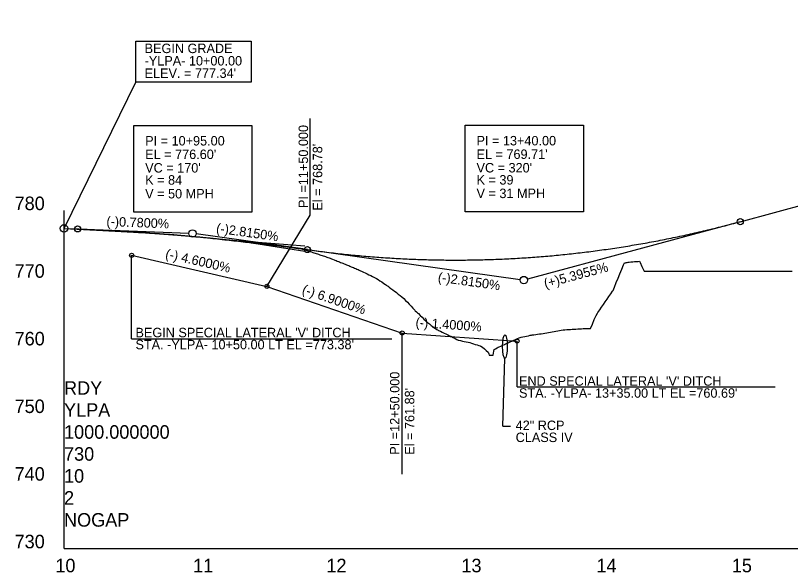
# Model space of a CAD drawing. Extents: x 579185 to 595036, y -53221 to -44640.
# Drawn here: x 579255 to 579828, y -51053 to -50642 of the extents above; entities that cross this region are included whole.
import ezdxf

# ---------------------------------------------------------------- set-up
doc = ezdxf.new("R2010")
doc.units = 0
for name, color, linetype in [('Default', 7, 'Continuous'), ('Exist Profile Cell', 7, 'Continuous'), ('Exist Vertical Profile Ground Line', 7, 'Continuous'), ('Exist Vertical Profile Horizontal Axis Label Major', 7, 'Continuous'), ('Exist Vertical Profile Vertical Axis Label', 7, 'Continuous'), ('Prop Grid Mask', 7, 'Continuous'), ('Prop PFL Cross Pipe CELL', 7, 'Continuous'), ('Prop Vertical Profile Curve Label', 7, 'Continuous'), ('Prop Vertical Profile Ditch Grade Left', 7, 'Continuous'), ('Prop Vertical Profile Ditch Grade Left Label', 7, 'Continuous'), ('Prop Vertical Profile Ditch Grade Right Label', 7, 'Continuous'), ('Prop Vertical Profile Grade', 7, 'Continuous'), ('Prop Vertical Profile Grade Label', 7, 'Continuous'), ('Prop VPI Ditch Grade Left Label', 7, 'Continuous'), ('Prop VPI Label', 7, 'Continuous')]:
    doc.layers.add(name, color=color, linetype=linetype)

msp = doc.modelspace()

# ---------------------------------------------------------------- linework, layer by layer
at = {"layer": 'Default'}
for points in [[(579290.38, -50799.07), (579318.98, -50800.49), (579368.86, -50803.42), (579418.21, -50807.98), (579468.45, -50812.02)], [(579290.38, -50799.07), (579318.98, -50800.49), (579368.86, -50803.42), (579418.21, -50808.04), (579468.45, -50815.9)]]:
    msp.add_lwpolyline(points, dxfattribs=at)
at = {"layer": 'Exist Profile Cell'}
for q in [(579290.38, -50785.8), (580388.15, -51035.8), (579290.38, -51035.8)]:
    msp.add_line((579290.38, -51035.8), q, dxfattribs=at)
at = {"layer": 'Exist Vertical Profile Ground Line'}
for points in [[(579290.38, -50799.07), (579297.26, -50799.41), (579300.7, -50799.58), (579304.13, -50799.75), (579305.9, -50799.84), (579307.57, -50799.92), (579308.34, -50799.96), (579311.01, -50800.09), (579314.45, -50800.26), (579317.88, -50800.44), (579321.32, -50800.61), (579324.76, -50800.79), (579326.48, -50800.88), (579328.2, -50800.97), (579329.92, -50801.06), (579331.27, -50801.13), (579331.63, -50801.15), (579332.4, -50801.19), (579333.35, -50801.25), (579335.07, -50801.35), (579336.79, -50801.45), (579338.51, -50801.55), (579340.23, -50801.66), (579341.95, -50801.76), (579343.67, -50801.87), (579345.38, -50801.98), (579347.1, -50802.08), (579348.82, -50802.19), (579350.54, -50802.3), (579352.26, -50802.41), (579353.52, -50802.49), (579353.98, -50802.52), (579355.7, -50802.63), (579357.42, -50802.74), (579358.51, -50802.82), (579359.13, -50802.86), (579360.85, -50802.99), (579362.57, -50803.11), (579364.29, -50803.24), (579366.08, -50803.38), (579367.73, -50803.5), (579369.45, -50803.63), (579371.17, -50803.76), (579372.88, -50803.89), (579374.6, -50804.02), (579376.32, -50804.15), (579378.04, -50804.29), (579379.76, -50804.42), (579381.48, -50804.56), (579383.2, -50804.7), (579384.92, -50804.87), (579386.63, -50805.03), (579388.35, -50805.2), (579390.07, -50805.37), (579391.79, -50805.54), (579393.51, -50805.71), (579395.23, -50805.89), (579396.95, -50806.06), (579398.67, -50806.24), (579400.38, -50806.42), (579402.1, -50806.6), (579403.82, -50806.83), (579405.54, -50807.06), (579406.15, -50807.14), (579407.26, -50807.21), (579408.98, -50807.37), (579409.29, -50807.4), (579410.7, -50807.55), (579412.42, -50807.74), (579414.13, -50807.94), (579415.85, -50808.13), (579417.57, -50808.33), (579419.29, -50808.53), (579421.01, -50808.73), (579422.73, -50808.94), (579424.45, -50809.15), (579426.17, -50809.36), (579427.88, -50809.57), (579428.74, -50809.68), (579429.06, -50809.72), (579429.6, -50809.78), (579430.46, -50809.89), (579431.32, -50810), (579432.18, -50810.11), (579433.04, -50810.22), (579433.9, -50810.32), (579434.76, -50810.43), (579435.71, -50810.56), (579436.48, -50810.65), (579437.34, -50810.75), (579438.2, -50810.85), (579439.06, -50810.95), (579439.92, -50811.05), (579440.77, -50811.15), (579441.66, -50811.26), (579442.49, -50811.31), (579443.35, -50811.37), (579444.21, -50811.43), (579445.07, -50811.49), (579445.93, -50811.55), (579446.79, -50811.61)], [(579446.79, -50811.61), (579447.65, -50811.67), (579448.58, -50811.73), (579449.37, -50811.83), (579450.23, -50811.94), (579451.09, -50812.06), (579451.95, -50812.17), (579452.81, -50812.28), (579453.67, -50812.4), (579454.52, -50812.51), (579455.38, -50812.63), (579456.24, -50812.75), (579457.1, -50812.86), (579457.96, -50812.98), (579458.82, -50813.1), (579459.68, -50813.22), (579460.54, -50813.34), (579461.4, -50813.46), (579462.26, -50813.58), (579463.12, -50813.7), (579463.98, -50813.82), (579464.84, -50813.95), (579465.94, -50814.15), (579466.65, -50814.36), (579467.42, -50814.6), (579468.27, -50814.86), (579469.13, -50815.13), (579469.99, -50815.4), (579470.85, -50815.67), (579471.71, -50815.95), (579472.57, -50816.22), (579473.43, -50816.5), (579474.29, -50816.78), (579475.15, -50817.06), (579476.01, -50817.35), (579476.87, -50817.63), (579477.73, -50817.92), (579478.59, -50818.21), (579479.45, -50818.5), (579480.31, -50818.79), (579481.17, -50819.09), (579482.02, -50819.37), (579482.88, -50819.66), (579483.74, -50819.94), (579484.6, -50820.23), (579485.46, -50820.53), (579486.32, -50820.83), (579487.18, -50821.18), (579488.04, -50821.53), (579488.9, -50821.88), (579490.02, -50822.35), (579490.62, -50822.57), (579491.48, -50822.89), (579492.34, -50823.22), (579493.2, -50823.54), (579494.06, -50823.87), (579494.92, -50824.2), (579495.77, -50824.53), (579496.63, -50824.87), (579497.49, -50825.2), (579498.35, -50825.54), (579499.21, -50825.89), (579500.07, -50826.23), (579500.93, -50826.58), (579501.79, -50826.93), (579502.81, -50827.35), (579503.51, -50827.65), (579504.37, -50828.02), (579505.23, -50828.4), (579506.09, -50828.78), (579506.95, -50829.16), (579507.81, -50829.55), (579508.67, -50829.94), (579509.52, -50830.33), (579510.38, -50830.72), (579511.74, -50831.35), (579513.09, -50831.98), (579514.45, -50832.62), (579515.8, -50833.27), (579517.16, -50833.93), (579518.51, -50834.59), (579519.87, -50835.33), (579521.33, -50836.14), (579522.58, -50836.94), (579523.93, -50837.81), (579525.29, -50838.68), (579526.82, -50839.68), (579528, -50840.46), (579528.88, -50841.05), (579529.35, -50841.4), (579529.94, -50841.84), (579530.71, -50842.42), (579532.06, -50843.44), (579533.42, -50844.47), (579534.78, -50845.51), (579535.1, -50845.77), (579536.13, -50846.54), (579537.49, -50847.57), (579538.84, -50848.62), (579540.2, -50849.69), (579541.55, -50850.82)], [(579652.66, -50875.38), (579654.02, -50875.14), (579655.37, -50874.89), (579656.73, -50874.65), (579658.08, -50874.4), (579659.44, -50874.16), (579660.79, -50873.95), (579662.15, -50873.88), (579663.5, -50873.81), (579664.86, -50873.74), (579666.21, -50873.66), (579667.57, -50873.59), (579668.92, -50873.51), (579670.28, -50873.43), (579671.63, -50873.35), (579672.99, -50873.26), (579674.34, -50873.18), (579675.17, -50873.13), (579675.7, -50873.13), (579677.05, -50873.14), (579678.41, -50873.14), (579679.76, -50873.11), (579681.12, -50869.8), (579682.47, -50866.49), (579683.08, -50865.02), (579683.92, -50863.37), (579684.77, -50861.75), (579685.18, -50861.15), (579686.54, -50859.2), (579687.9, -50857.26), (579689.25, -50855.27), (579690.61, -50853.28), (579691.96, -50851.3), (579693.32, -50849.32), (579694.67, -50847.35), (579696.03, -50845.39), (579696.35, -50844.92), (579697.38, -50842.41), (579698.74, -50839.11), (579700.09, -50835.83), (579701.45, -50832.56), (579702.8, -50829.3), (579704.16, -50826.05), (579704.76, -50824.62), (579705.51, -50824.43), (579706.04, -50824.31), (579706.87, -50824.15), (579707.54, -50824.02), (579708.22, -50823.96), (579709.58, -50823.84), (579710.93, -50823.73), (579712.29, -50823.61), (579713.64, -50823.49), (579714, -50823.46), (579715, -50823.41), (579715.88, -50823.37), (579716.35, -50824.36), (579717.71, -50827.18), (579719.26, -50830.66), (579719.87, -50830.66), (579720.42, -50830.66), (579721.77, -50830.66), (579723.13, -50830.66), (579724.48, -50830.66), (579725.84, -50830.66), (579727.19, -50830.66), (579728.55, -50830.66), (579729.9, -50830.66), (579730.94, -50830.66), (579731.26, -50830.66), (579732.61, -50830.66), (579733.97, -50830.66), (579735.32, -50830.66), (579736.68, -50830.66), (579738.03, -50830.66), (579739.39, -50830.66), (579740.74, -50830.66), (579742.1, -50830.66), (579743.45, -50830.66), (579744.81, -50830.66), (579746.16, -50830.66), (579747.52, -50830.66), (579748.87, -50830.66), (579750.23, -50830.66), (579751.58, -50830.66), (579752.94, -50830.66), (579754.29, -50830.66), (579755.65, -50830.66), (579757, -50830.66), (579758.36, -50830.66), (579759.71, -50830.66), (579761.07, -50830.66), (579761.58, -50830.66), (579762.42, -50830.66), (579763.78, -50830.66), (579765.13, -50830.66), (579766.49, -50830.66), (579766.95, -50830.66), (579767.84, -50830.66), (579769.2, -50830.66), (579770.55, -50830.66)], [(579770.55, -50830.66), (579771.22, -50830.66), (579771.91, -50830.66), (579773.37, -50830.66), (579774.62, -50830.66), (579775.97, -50830.66), (579777.33, -50830.66), (579777.94, -50830.66), (579778.68, -50830.66), (579780.04, -50830.66), (579781.39, -50830.66), (579782.75, -50830.66), (579784.1, -50830.66), (579785.46, -50830.66), (579786.81, -50830.66), (579788.17, -50830.66), (579789.52, -50830.66), (579790.88, -50830.66), (579792.23, -50830.66), (579793.59, -50830.66), (579794.94, -50830.66), (579796.3, -50830.66), (579797.65, -50830.66), (579799.01, -50830.66), (579800.36, -50830.66), (579801.72, -50830.66), (579803.07, -50830.66), (579804.43, -50830.66), (579805.78, -50830.66), (579807.14, -50830.66), (579808.49, -50830.66), (579809.85, -50830.66), (579811.2, -50830.66), (579812.56, -50830.66), (579813.18, -50830.66), (579813.91, -50830.66), (579815.27, -50830.66), (579816.66, -50830.66), (579817.98, -50830.66), (579819.33, -50830.66), (579820.69, -50830.66), (579822.04, -50830.66), (579823.4, -50830.66), (579824.79, -50830.66), (579826.11, -50830.66), (579827.46, -50830.66), (579828.82, -50830.66)], [(579541.55, -50850.82), (579542.91, -50852.25), (579544.26, -50853.69), (579545.62, -50855.13), (579546.97, -50856.58), (579548.33, -50858.05), (579549.68, -50859.52), (579550.06, -50859.93), (579551.04, -50860.82), (579551.81, -50861.54), (579552.39, -50862.09), (579553.75, -50863.41), (579555.1, -50864.73), (579556.46, -50866.06), (579557.81, -50867.4), (579558.51, -50868.1), (579559.17, -50868.61), (579560.52, -50869.67), (579561.88, -50870.74), (579563.23, -50871.81), (579564.07, -50872.47), (579564.59, -50872.81), (579565.94, -50873.7), (579566.97, -50874.38), (579567.3, -50874.52), (579568.65, -50875.14), (579570.01, -50875.76), (579570.58, -50876.02), (579571.36, -50876.4), (579572.72, -50877.07), (579574.07, -50877.73), (579575.43, -50878.4), (579576.31, -50878.83), (579576.78, -50879.07), (579578.14, -50879.77), (579578.72, -50880.07), (579579.49, -50880.48), (579580.85, -50881.19), (579581.76, -50881.67), (579582.2, -50881.78), (579583.56, -50882.05), (579584.91, -50882.31), (579586.27, -50882.58), (579587.62, -50882.84), (579589.15, -50883.13), (579590.33, -50883.51), (579591.69, -50883.94), (579593.04, -50884.37), (579594.4, -50884.8), (579595.75, -50885.22), (579597.11, -50885.64), (579597.97, -50885.91), (579598.46, -50886.09), (579599.82, -50886.83), (579601.17, -50888.04), (579602.53, -50889.24), (579603.91, -50890.46), (579604.46, -50891.9), (579604.81, -50892.8), (579605.31, -50892.73), (579606.59, -50892.79), (579607.6, -50892.84), (579608.05, -50889.89), (579608.49, -50888.7), (579609.3, -50888.21), (579610.66, -50887.39), (579611.4, -50886.93), (579612.01, -50886.67), (579613.37, -50886.09), (579614.35, -50885.67), (579614.72, -50885.49), (579616.08, -50884.81), (579616.73, -50884.48), (579617.43, -50884.16), (579618.79, -50883.54), (579620.14, -50882.92), (579621.5, -50882.31), (579622.85, -50881.69), (579624.21, -50881.08), (579625.56, -50880.44), (579626.92, -50879.84), (579628.27, -50879.55), (579629.63, -50879.26), (579630.98, -50878.97), (579632.34, -50878.68), (579633.69, -50878.39), (579635.05, -50878.1), (579636, -50877.9), (579636.4, -50877.85), (579637.76, -50877.67), (579639.25, -50877.48), (579640.47, -50877.3), (579641.82, -50877.11), (579643.18, -50876.92), (579644.53, -50876.73), (579645.89, -50876.53), (579647.24, -50876.33), (579648.65, -50876.11), (579649.95, -50875.87), (579651.31, -50875.63), (579652.66, -50875.38)]]:
    msp.add_lwpolyline(points, dxfattribs=at)
at = {"layer": 'Prop Grid Mask'}
for points in [[(579343.41, -50660.71), (579428.8, -50660.71), (579428.8, -50690.9), (579343.41, -50690.9)], [(579342, -50722.89), (579429.36, -50722.89), (579429.36, -50787.07), (579342, -50787.07)], [(579587, -50722.66), (579674.36, -50722.66), (579674.36, -50786.83), (579587, -50786.83)]]:
    msp.add_lwpolyline(points, close=True, dxfattribs=at)
at = {"layer": 'Prop PFL Cross Pipe CELL'}
msp.add_ellipse((579616.38, -50886.4), major_axis=(0, 8.75), ratio=0.2, dxfattribs=at)
at = {"layer": 'Prop Vertical Profile Curve Label'}
msp.add_line((579290.38, -50799.07), (579343.41, -50690.9), dxfattribs=at)
for centre in [(579790.38, -50794.1), (579300.38, -50799.46), (579470.38, -50814.74), (579470.38, -50814.74)]:
    msp.add_circle(centre, 2.25, dxfattribs=at)
at = {"layer": 'Prop Vertical Profile Ditch Grade Left'}
msp.add_lwpolyline([(579340.38, -50818.9), (579440.38, -50841.9), (579540.38, -50876.4), (579625.38, -50882.35)], dxfattribs=at)
at = {"layer": 'Prop Vertical Profile Ditch Grade Left Label'}
for p, q in [((579472.35, -50789.18), (579472.35, -50717.76)), ((579440.38, -50841.9), (579472.35, -50789.18)), ((579340.38, -50880.65), (579340.38, -50818.9)), ((579540.38, -50980.69), (579540.38, -50876.4)), ((579340.38, -50880.65), (579532.84, -50880.65)), ((579625.38, -50916.13), (579625.38, -50882.35)), ((579625.38, -50916.13), (579816.19, -50916.13))]:
    msp.add_line(p, q, dxfattribs=at)
for centre in [(579340.38, -50818.9), (579440.38, -50841.9), (579540.38, -50876.4), (579625.38, -50882.35)]:
    msp.add_circle(centre, 1.5, dxfattribs=at)
at = {"layer": 'Prop Vertical Profile Ditch Grade Right Label'}
for q in [(579616.38, -50895.15), (579620.42, -50945.27)]:
    msp.add_line((579614.8, -50945.27), q, dxfattribs=at)
at = {"layer": 'Prop Vertical Profile Grade'}
for p, q in [((579790.38, -50794.1), (580355.39, -50641.67)), ((579290.38, -50799.07), (579300.38, -50799.46))]:
    msp.add_line(p, q, dxfattribs=at)
for points in [[(579470.38, -50814.74), (579476.78, -50815.62), (579483.18, -50816.44), (579489.58, -50817.21), (579495.98, -50817.92), (579502.38, -50818.59), (579508.78, -50819.2), (579515.18, -50819.76), (579521.58, -50820.27), (579527.98, -50820.72), (579534.38, -50821.12), (579540.78, -50821.47), (579547.18, -50821.77), (579553.58, -50822.01), (579559.98, -50822.2), (579566.38, -50822.34), (579572.78, -50822.43), (579579.18, -50822.46), (579585.58, -50822.44), (579591.98, -50822.37), (579598.38, -50822.25), (579604.78, -50822.07), (579611.18, -50821.84), (579617.58, -50821.56), (579623.98, -50821.23), (579630.38, -50820.84), (579636.78, -50820.4), (579643.18, -50819.91), (579649.58, -50819.37), (579655.98, -50818.77), (579662.38, -50818.12), (579668.78, -50817.42), (579675.18, -50816.66), (579681.58, -50815.86), (579687.98, -50815), (579694.38, -50814.08), (579700.78, -50813.12), (579707.18, -50812.1), (579713.58, -50811.03), (579719.98, -50809.91), (579726.38, -50808.74), (579732.78, -50807.51), (579739.18, -50806.23), (579745.58, -50804.9), (579751.98, -50803.51), (579758.38, -50802.07), (579764.78, -50800.58), (579771.18, -50799.04), (579777.58, -50797.45), (579783.98, -50795.8), (579790.38, -50794.1)], [(579300.38, -50799.46), (579303.78, -50799.6), (579307.18, -50799.74), (579310.58, -50799.89), (579313.98, -50800.05), (579317.38, -50800.21), (579320.78, -50800.38), (579324.18, -50800.56), (579327.58, -50800.74), (579330.98, -50800.94), (579334.38, -50801.13), (579337.78, -50801.34), (579341.18, -50801.55), (579344.58, -50801.77), (579347.98, -50802), (579351.38, -50802.23), (579354.78, -50802.47), (579358.18, -50802.72), (579361.58, -50802.97), (579364.98, -50803.23), (579368.38, -50803.5), (579371.78, -50803.77), (579375.18, -50804.05), (579378.58, -50804.34), (579381.98, -50804.64), (579385.38, -50804.94), (579388.78, -50805.25), (579392.18, -50805.56), (579395.58, -50805.89), (579398.98, -50806.22), (579402.38, -50806.55), (579405.78, -50806.9), (579409.18, -50807.25), (579412.58, -50807.61), (579415.98, -50807.97), (579419.38, -50808.34), (579422.78, -50808.72), (579426.18, -50809.11), (579429.58, -50809.5), (579432.98, -50809.9), (579436.38, -50810.3), (579439.78, -50810.71), (579443.18, -50811.13), (579446.58, -50811.56), (579449.98, -50811.99), (579453.38, -50812.44), (579456.78, -50812.88), (579460.18, -50813.34), (579463.58, -50813.8), (579466.98, -50814.27), (579470.38, -50814.74)]]:
    msp.add_spline(points, degree=3, dxfattribs=at)
at = {"layer": 'Prop VPI Label'}
for p, q in [((579790.38, -50794.1), (579633.04, -50836.55)), ((579300.38, -50799.46), (579382.64, -50802.67)), ((579470.38, -50814.74), (579388.11, -50803.16)), ((579470.38, -50814.74), (579627.66, -50836.88))]:
    msp.add_line(p, q, dxfattribs=at)
for centre in [(579290.38, -50799.07), (579385.38, -50802.78), (579630.38, -50837.26)]:
    msp.add_circle(centre, 2.75, dxfattribs=at)

# ---------------------------------------------------------------- texts
at = {"layer": 'Exist Profile Cell'}
for s, p in [('RDY', (579290.38, -50922.05)), ('YLPA', (579290.38, -50938.3)), ('1000.000000', (579290.38, -50954.55)), ('730', (579290.38, -50970.8)), ('10', (579290.38, -50987.05)), ('2', (579290.38, -51003.3)), ('NOGAP', (579290.38, -51019.55))]:
    msp.add_text(s, height=10, dxfattribs=at).set_placement(p)
at = {"layer": 'Exist Vertical Profile Horizontal Axis Label Major'}
for s, p in [('10', (579283.97, -51053.3)), ('11', (579385.81, -51053.3)), ('12', (579484.36, -51053.3)), ('13', (579584.19, -51053.3)), ('14', (579684.03, -51053.3)), ('15', (579784.13, -51053.3))]:
    msp.add_text(s, height=10, dxfattribs=at).set_placement(p)
at = {"layer": 'Exist Vertical Profile Vertical Axis Label'}
for s, p in [('780', (579253.82, -50785.55)), ('770', (579253.82, -50835.55)), ('760', (579253.82, -50885.55)), ('750', (579253.82, -50935.55)), ('740', (579253.82, -50985.55)), ('730', (579253.82, -51035.55))]:
    msp.add_text(s, height=10, dxfattribs=at).set_placement(p)
at = {"layer": 'Prop Vertical Profile Curve Label'}
for s, p in [("VC = 170'", (579350.38, -50757.78)), ("VC = 320'", (579595.38, -50757.71)), ('K = 84', (579350.38, -50766.73)), ('K = 39', (579595.38, -50766.66)), ('V = 31 MPH', (579595.38, -50776.66)), ('V = 50 MPH', (579350.38, -50776.9))]:
    msp.add_text(s, height=7, dxfattribs=at).set_placement(p)
at = {"layer": 'Prop Vertical Profile Ditch Grade Left Label'}
for s, rotation, p in [('(-) 4.6000%', 347.04724, (579364.87, -50820.94)), ('(-) 6.9000%', 340.96557, (579465.83, -50846.98)), ('(-) 1.4000%', 355.99583, (579550.14, -50871.88))]:
    msp.add_text(s, height=7, rotation=rotation, dxfattribs=at).set_placement(p)
for s, p in [("BEGIN SPECIAL LATERAL 'V' DITCH", (579343.21, -50879.55)), ("STA. -YLPA- 10+50.00 LT EL =773.38'", (579343.21, -50888.42)), ("END SPECIAL LATERAL 'V' DITCH", (579626.78, -50915.37)), ("STA. -YLPA- 13+35.00 LT EL =760.69'", (579626.78, -50924.25))]:
    msp.add_text(s, height=7, dxfattribs=at).set_placement(p)
at = {"layer": 'Prop Vertical Profile Ditch Grade Right Label'}
for s, p in [('42" RCP', (579624.31, -50948.14)), ('CLASS IV', (579624.31, -50957.01))]:
    msp.add_text(s, height=7, dxfattribs=at).set_placement(p)
at = {"layer": 'Prop Vertical Profile Grade Label'}
for s, rotation, p in [('(-)0.7800%', 357.7666, (579321.62, -50797.29)), ('(-)2.8150%', 351.98825, (579402.55, -50802.16)), ('(+)5.3955%', 15.0975, (579646.29, -50843.33)), ('(-)2.8150%', 351.98825, (579566.52, -50838.37))]:
    msp.add_text(s, height=7, rotation=rotation, dxfattribs=at).set_placement(p)
at = {"layer": 'Prop VPI Ditch Grade Left Label'}
for s, p in [('PI =11+50.000', (579470.81, -50784.02)), ("El = 768.78'", (579481.33, -50785.93)), ('PI =12+50.000', (579538.38, -50966.4)), ("El = 761.88'", (579549.38, -50966.4))]:
    msp.add_text(s, height=7, rotation=90, dxfattribs=at).set_placement(p)
at = {"layer": 'Prop VPI Label'}
for s, p in [('BEGIN GRADE', (579349.96, -50669.47)), ('-YLPA- 10+00.00', (579349.96, -50678.64)), ("ELEV. = 777.34'", (579349.96, -50687.82)), ('PI = 10+95.00', (579350.38, -50737.78)), ('PI = 13+40.00', (579595.38, -50737.71)), ("EL = 776.60'", (579350.38, -50747.78)), ("EL = 769.71'", (579595.38, -50747.71))]:
    msp.add_text(s, height=7, dxfattribs=at).set_placement(p)

doc.saveas('drawing.dxf')
